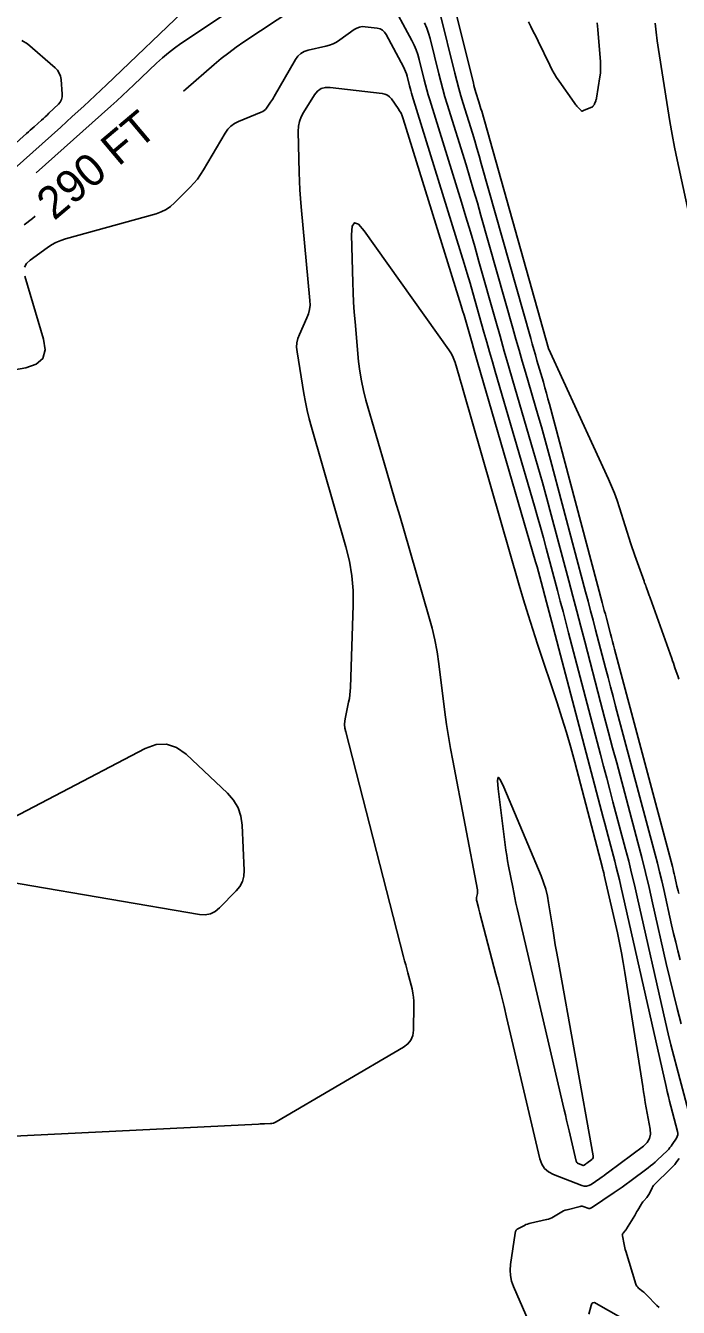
# Model space of a CAD drawing. Extents: x 1768942 to 1774819, y 723037 to 732099.
# Drawn here: x 1770546.4 to 1770667.5, y 726239 to 726476.9 of the extents above; entities that cross this region are included whole.
import ezdxf

# ---------------------------------------------------------------- set-up
doc = ezdxf.new("R2010")
doc.units = 0
doc.layers.add('R_Contour Annot', color=7, linetype='Continuous')
doc.layers.add('R_Contours', color=7, linetype='Continuous')

msp = doc.modelspace()

# ---------------------------------------------------------------- linework, layer by layer
at = {"layer": 'R_Contours'}
for points in [[(1770548.33, 726449.52), (1770562.19, 726461.9), (1770563.27, 726462.88), (1770564.35, 726463.86), (1770565.41, 726464.85), (1770566.47, 726465.85), (1770570.67, 726469.88), (1770571.74, 726470.86), (1770572.85, 726471.79), (1770574, 726472.68), (1770575.19, 726473.52), (1770592.17, 726484.94)], [(1770625, 726484.06), (1770629.42, 726466.21), (1770629.53, 726465.76), (1770629.65, 726465.32), (1770629.77, 726464.89), (1770629.91, 726464.45), (1770630.45, 726462.7), (1770630.58, 726462.27), (1770630.71, 726461.83), (1770630.84, 726461.39), (1770630.97, 726460.95), (1770643.37, 726416.95), (1770643.37, 726416.95), (1770643.38, 726416.93), (1770643.38, 726416.93), (1770654.49, 726392.69), (1770655.07, 726391.39), (1770655.6, 726390.08), (1770656.09, 726388.74), (1770656.53, 726387.4), (1770658.65, 726380.7), (1770658.88, 726379.98), (1770659.12, 726379.27), (1770659.36, 726378.56), (1770659.61, 726377.85), (1770661.08, 726373.76), (1770661.11, 726373.68), (1770661.14, 726373.61), (1770661.16, 726373.53), (1770661.2, 726373.46), (1770661.35, 726373.08), (1770661.37, 726373.05), (1770661.38, 726373.01), (1770661.39, 726372.98), (1770661.41, 726372.95), (1770661.45, 726372.82), (1770661.47, 726372.79), (1770661.48, 726372.75), (1770661.49, 726372.72), (1770661.5, 726372.69), (1770661.92, 726371.5), (1770661.99, 726371.3), (1770662.06, 726371.09), (1770662.14, 726370.88), (1770662.21, 726370.67), (1770666.23, 726359.4), (1770666.39, 726358.98), (1770666.53, 726358.55), (1770666.68, 726358.13), (1770666.83, 726357.7), (1770667.41, 726356), (1770667.55, 726355.57)], [(1770576.87, 726480.72), (1770561.38, 726465.89), (1770559.27, 726463.9), (1770557.16, 726461.92), (1770555.02, 726459.97), (1770552.87, 726458.03), (1770544.22, 726450.31)], [(1770596.1, 726479.98), (1770586.87, 726473.83), (1770585.44, 726472.85), (1770584.04, 726471.82), (1770582.67, 726470.75), (1770581.34, 726469.63), (1770576.08, 726465.08), (1770575.63, 726464.69)], [(1770667.97, 726291.65), (1770667.24, 726294.44), (1770666.54, 726297.23), (1770665.87, 726300.03), (1770665.22, 726302.84), (1770662.68, 726314.09), (1770662.04, 726316.9), (1770661.36, 726319.7), (1770660.66, 726322.5), (1770659.93, 726325.28), (1770656.01, 726340.05), (1770655.26, 726342.87), (1770654.52, 726345.68), (1770653.78, 726348.49), (1770653.04, 726351.31), (1770650.09, 726362.56), (1770649.35, 726365.38), (1770648.61, 726368.19), (1770647.87, 726371), (1770647.12, 726373.81), (1770643.85, 726386.1), (1770643.05, 726389.08), (1770642.23, 726392.06), (1770641.39, 726395.03), (1770640.54, 726398), (1770636.77, 726410.94), (1770635.97, 726413.7), (1770635.17, 726416.47), (1770634.38, 726419.23), (1770633.6, 726422), (1770630.47, 726433.08), (1770629.68, 726435.85), (1770628.88, 726438.61), (1770628.05, 726441.36), (1770627.21, 726444.12), (1770621.32, 726463.08), (1770621.04, 726464), (1770620.78, 726464.93), (1770620.53, 726465.86), (1770620.29, 726466.8), (1770619.36, 726470.54), (1770619.1, 726471.47), (1770618.79, 726472.37), (1770618.42, 726473.25), (1770617.99, 726474.11), (1770613.86, 726481.82)], [(1770667.52, 726315.83), (1770667.4, 726316.28), (1770667.3, 726316.73), (1770667.19, 726317.19), (1770666.78, 726318.99), (1770666.68, 726319.45), (1770666.57, 726319.9), (1770666.46, 726320.35), (1770666.34, 726320.79), (1770655.62, 726361.13), (1770655.43, 726361.86), (1770655.24, 726362.58), (1770655.05, 726363.3), (1770654.86, 726364.02), (1770654.1, 726366.91), (1770653.91, 726367.63), (1770653.72, 726368.35), (1770653.53, 726369.08), (1770653.34, 726369.8), (1770643.55, 726406.6), (1770643.27, 726407.62), (1770642.99, 726408.64), (1770642.71, 726409.66), (1770642.41, 726410.68), (1770641.23, 726414.74), (1770640.93, 726415.76), (1770640.64, 726416.78), (1770640.35, 726417.8), (1770640.06, 726418.81), (1770630.9, 726451.3), (1770630.51, 726452.7), (1770630.1, 726454.09), (1770629.68, 726455.48), (1770629.26, 726456.87), (1770627.54, 726462.42), (1770627.12, 726463.8), (1770626.72, 726465.2), (1770626.34, 726466.6), (1770625.98, 726468.01), (1770623.19, 726479.26)], [(1770546.18, 726432.03), (1770546.56, 726432.74), (1770547.21, 726433.35), (1770550.35, 726435.64), (1770551.15, 726436.17), (1770551.99, 726436.62), (1770552.87, 726437), (1770553.79, 726437.3), (1770570.59, 726441.96), (1770571.54, 726442.29), (1770572.43, 726442.73), (1770573.25, 726443.29), (1770574, 726443.95), (1770576.89, 726446.85), (1770577.58, 726447.6), (1770578.23, 726448.38), (1770578.82, 726449.2), (1770579.36, 726450.07), (1770583.36, 726456.92), (1770583.85, 726457.62), (1770584.42, 726458.21), (1770585.09, 726458.69), (1770585.85, 726459.07), (1770590.07, 726460.78), (1770590.36, 726460.92), (1770590.62, 726461.1), (1770590.85, 726461.31), (1770591.05, 726461.56), (1770591.8, 726462.62), (1770591.99, 726462.89), (1770592.17, 726463.16), (1770592.34, 726463.44), (1770592.5, 726463.72), (1770596.43, 726470.55), (1770596.88, 726471.18), (1770597.42, 726471.68), (1770598.06, 726472.05), (1770598.79, 726472.29), (1770602.05, 726473.02), (1770602.75, 726473.21), (1770603.42, 726473.48), (1770604.06, 726473.8), (1770604.68, 726474.2), (1770607.34, 726476.13), (1770607.81, 726476.41), (1770608.3, 726476.59), (1770608.82, 726476.67), (1770609.36, 726476.64), (1770611.59, 726476.36), (1770612.11, 726476.24), (1770612.55, 726476.01), (1770612.93, 726475.67), (1770613.23, 726475.23), (1770616.47, 726469.19), (1770616.67, 726468.77), (1770616.85, 726468.35), (1770617, 726467.92), (1770617.13, 726467.48), (1770617.57, 726465.69), (1770617.68, 726465.24), (1770617.8, 726464.8), (1770617.93, 726464.35), (1770618.06, 726463.91), (1770627.19, 726434.5), (1770627.74, 726432.69), (1770628.29, 726430.87), (1770628.82, 726429.06), (1770629.34, 726427.24), (1770631.39, 726419.95), (1770631.91, 726418.13), (1770632.43, 726416.31), (1770632.95, 726414.49), (1770633.48, 726412.67), (1770640.76, 726387.67), (1770641.32, 726385.72), (1770641.87, 726383.77), (1770642.41, 726381.82), (1770642.94, 726379.86), (1770645.02, 726372.03), (1770645.54, 726370.07), (1770646.06, 726368.11), (1770646.57, 726366.15), (1770647.09, 726364.19), (1770653, 726341.63), (1770653.58, 726339.43), (1770654.16, 726337.23), (1770654.74, 726335.03), (1770655.32, 726332.83), (1770657.66, 726324.02), (1770658.24, 726321.82), (1770658.79, 726319.61), (1770659.32, 726317.4), (1770659.83, 726315.18), (1770665.08, 726291.91), (1770665.57, 726289.8), (1770666.08, 726287.7), (1770666.6, 726285.6), (1770667.15, 726283.51), (1770670.06, 726272.56)], [(1770620.38, 726477.35), (1770620.78, 726476.41), (1770621.11, 726475.45), (1770621.39, 726474.47), (1770623.01, 726467.91), (1770623.37, 726466.48), (1770623.75, 726465.07), (1770624.16, 726463.66), (1770624.58, 726462.25), (1770628.06, 726451.03), (1770628.78, 726448.69), (1770629.48, 726446.35), (1770630.17, 726444), (1770630.84, 726441.65), (1770636.75, 726420.7), (1770637.32, 726418.66), (1770637.91, 726416.62), (1770638.49, 726414.59), (1770639.08, 726412.55), (1770641.45, 726404.42), (1770642.04, 726402.39), (1770642.61, 726400.35), (1770643.17, 726398.31), (1770643.72, 726396.26), (1770650.23, 726371.81), (1770650.7, 726370.04), (1770651.17, 726368.27), (1770651.63, 726366.5), (1770652.09, 726364.74), (1770653.95, 726357.66), (1770654.41, 726355.9), (1770654.88, 726354.13), (1770655.34, 726352.36), (1770655.81, 726350.59), (1770663.14, 726323.04), (1770663.56, 726321.42), (1770663.97, 726319.8), (1770664.36, 726318.17), (1770664.73, 726316.54), (1770666.21, 726310.01), (1770666.58, 726308.38), (1770666.97, 726306.76), (1770667.38, 726305.14), (1770667.8, 726303.52)], [(1770652.39, 726477.36), (1770652.49, 726476.13), (1770652.99, 726470.12), (1770653.03, 726469.42), (1770653.03, 726468.72), (1770652.98, 726468.02), (1770652.89, 726467.33), (1770652.26, 726463.39), (1770652.24, 726463.27), (1770652.21, 726463.16), (1770652.17, 726463.04), (1770652.13, 726462.92), (1770651.92, 726462.35), (1770651.89, 726462.3), (1770651.87, 726462.24), (1770651.84, 726462.19), (1770651.81, 726462.14), (1770651.68, 726461.94), (1770651.65, 726461.9), (1770651.61, 726461.86), (1770651.56, 726461.82), (1770651.51, 726461.8), (1770649.87, 726461.09), (1770649.87, 726461.09), (1770649.87, 726461.09), (1770649.86, 726461.09), (1770649.86, 726461.09), (1770649.85, 726461.1), (1770649.85, 726461.1), (1770649.84, 726461.1), (1770649.84, 726461.1), (1770649.84, 726461.1), (1770649.62, 726461.01), (1770649.58, 726461), (1770649.55, 726461), (1770649.51, 726461.01), (1770649.48, 726461.03), (1770648.64, 726461.91), (1770648.5, 726462.07), (1770648.36, 726462.23), (1770648.22, 726462.4), (1770648.1, 726462.57), (1770645.36, 726466.52), (1770644.87, 726467.24), (1770644.42, 726467.98), (1770643.99, 726468.74), (1770643.6, 726469.52), (1770641.43, 726473.97), (1770640.99, 726474.87), (1770640.55, 726475.77), (1770640.1, 726476.67), (1770639.66, 726477.57)], [(1770672.35, 726428.26), (1770667.23, 726451.97), (1770666.74, 726454.32), (1770666.28, 726456.68), (1770665.86, 726459.04), (1770665.47, 726461.41), (1770663.76, 726472.4), (1770663.52, 726474.02), (1770663.32, 726475.64), (1770663.16, 726477.28)], [(1770545.69, 726474.12), (1770546.71, 726473.46), (1770551.86, 726469.01), (1770552.29, 726468.56), (1770552.61, 726468.05), (1770552.83, 726467.49), (1770552.94, 726466.88), (1770553.16, 726464.15), (1770553.15, 726463.61), (1770553.03, 726463.12), (1770552.79, 726462.67), (1770552.45, 726462.26), (1770550.69, 726460.58), (1770550.35, 726460.26), (1770550.01, 726459.94), (1770549.67, 726459.63), (1770549.32, 726459.31), (1770547.93, 726458.07), (1770547.58, 726457.76), (1770547.23, 726457.45), (1770546.88, 726457.13), (1770546.53, 726456.82), (1770526.78, 726439.08)], [(1770540.37, 726270.59), (1770589.57, 726273.02), (1770589.85, 726273.04), (1770590.12, 726273.05), (1770590.4, 726273.06), (1770590.68, 726273.07), (1770591.79, 726273.12), (1770592.06, 726273.15), (1770592.33, 726273.21), (1770592.58, 726273.3), (1770592.83, 726273.43), (1770616.49, 726287.32), (1770617.27, 726287.91), (1770617.84, 726288.62), (1770618.18, 726289.46), (1770618.31, 726290.43), (1770618.41, 726295.07), (1770618.4, 726295.83), (1770618.33, 726296.59), (1770618.22, 726297.34), (1770618.05, 726298.09), (1770617.26, 726301.06), (1770617.07, 726301.81), (1770616.87, 726302.55), (1770616.68, 726303.29), (1770616.49, 726304.04), (1770605.74, 726345.81), (1770605.6, 726346.49), (1770605.55, 726347.17), (1770605.58, 726347.86), (1770605.69, 726348.54), (1770606.29, 726351.29), (1770606.42, 726351.97), (1770606.53, 726352.67), (1770606.6, 726353.36), (1770606.64, 726354.06), (1770607.14, 726369.29), (1770607.12, 726372.05), (1770606.89, 726374.78), (1770606.45, 726377.48), (1770605.79, 726380.16), (1770599.4, 726402.36), (1770598.98, 726403.9), (1770598.61, 726405.45), (1770598.28, 726407), (1770598, 726408.57), (1770596.72, 726416.35), (1770596.64, 726417.17), (1770596.69, 726417.98), (1770596.86, 726418.77), (1770597.15, 726419.55), (1770598.56, 726422.62), (1770598.85, 726423.39), (1770599.04, 726424.19), (1770599.13, 726425), (1770599.1, 726425.83), (1770597.5, 726443.21), (1770597.37, 726444.8), (1770597.26, 726446.39), (1770597.19, 726447.98), (1770597.13, 726449.57), (1770596.95, 726457.23), (1770597, 726458.17), (1770597.17, 726459.07), (1770597.48, 726459.93), (1770597.93, 726460.76), (1770599.97, 726464), (1770600.53, 726464.69), (1770601.21, 726465.16), (1770601.99, 726465.39), (1770602.89, 726465.39), (1770612.51, 726464.27), (1770613.02, 726464.16), (1770613.48, 726463.96), (1770613.87, 726463.66), (1770614.21, 726463.26), (1770615.46, 726461.5), (1770615.75, 726461.05), (1770616.01, 726460.58), (1770616.23, 726460.09), (1770616.4, 726459.58), (1770627.17, 726424.88), (1770627.44, 726424.01), (1770627.7, 726423.14), (1770627.95, 726422.27), (1770628.2, 726421.4), (1770629.19, 726417.9), (1770629.43, 726417.03), (1770629.68, 726416.15), (1770629.93, 726415.28), (1770630.19, 726414.41), (1770640.98, 726377.34), (1770641.25, 726376.42), (1770641.51, 726375.49), (1770641.77, 726374.56), (1770642.02, 726373.62), (1770643.01, 726369.89), (1770643.26, 726368.96), (1770643.51, 726368.02), (1770643.75, 726367.09), (1770644, 726366.16), (1770653.18, 726331.09), (1770653.49, 726329.93), (1770653.79, 726328.78), (1770654.1, 726327.62), (1770654.41, 726326.46), (1770655.64, 726321.84), (1770655.94, 726320.68), (1770656.23, 726319.52), (1770656.51, 726318.36), (1770656.78, 726317.19), (1770665.17, 726279.97), (1770665.38, 726279.06), (1770665.6, 726278.16), (1770665.83, 726277.26), (1770666.06, 726276.36), (1770667.31, 726271.66), (1770667.37, 726271.33), (1770667.35, 726271), (1770667.26, 726270.69), (1770667.1, 726270.39), (1770666.32, 726269.21), (1770666.11, 726268.92), (1770665.9, 726268.65), (1770665.66, 726268.39), (1770665.41, 726268.13), (1770663.52, 726266.34), (1770663.12, 726265.97), (1770662.7, 726265.61), (1770662.28, 726265.26), (1770661.84, 726264.92), (1770658.46, 726262.38), (1770657.75, 726261.86), (1770657.02, 726261.34), (1770656.3, 726260.83), (1770655.56, 726260.32), (1770651.35, 726257.48), (1770651.18, 726257.39), (1770651.02, 726257.35), (1770650.85, 726257.35), (1770650.67, 726257.4), (1770649.95, 726257.68), (1770649.78, 726257.73), (1770649.59, 726257.76), (1770649.41, 726257.76), (1770649.23, 726257.73), (1770646.8, 726257.13), (1770646.46, 726257.03), (1770646.13, 726256.9), (1770645.81, 726256.75), (1770645.51, 726256.58), (1770644.31, 726255.82), (1770644.01, 726255.65), (1770643.69, 726255.5), (1770643.36, 726255.38), (1770643.02, 726255.29), (1770640.04, 726254.64), (1770639.75, 726254.57), (1770639.45, 726254.47), (1770639.17, 726254.36), (1770638.89, 726254.23), (1770637.79, 726253.67), (1770637.55, 726253.51), (1770637.36, 726253.31), (1770637.23, 726253.07), (1770637.15, 726252.78), (1770636.31, 726246.99), (1770636.23, 726245.94), (1770636.3, 726244.9), (1770636.51, 726243.89), (1770636.87, 726242.89), (1770640.85, 726233.8)], [(1770548.11, 726441.49), (1770547.62, 726441.08), (1770546.07, 726439.88)], [(1770517.93, 726408.32), (1770546.41, 726413.37), (1770548.35, 726414.01), (1770549.55, 726415.11), (1770549.99, 726416.67), (1770549.69, 726418.69), (1770546.2, 726430.35)], [(1770534.98, 726325.17), (1770568.53, 726342.7), (1770570.57, 726343.45), (1770572.51, 726343.53), (1770574.36, 726342.93), (1770576.12, 726341.66), (1770583.82, 726334.42), (1770584.96, 726333.14), (1770585.79, 726331.72), (1770586.32, 726330.16), (1770586.55, 726328.46), (1770586.89, 726320.06), (1770586.84, 726319), (1770586.58, 726318.01), (1770586.11, 726317.11), (1770585.44, 726316.28), (1770582.34, 726313.13), (1770581.53, 726312.46), (1770580.64, 726312.04), (1770579.67, 726311.86), (1770578.62, 726311.92), (1770528.69, 726320.45)], [(1770667.6, 726266.63), (1770667.2, 726266.07), (1770666.78, 726265.53), (1770666.32, 726265.01), (1770665.83, 726264.52), (1770663.2, 726262.02), (1770663.01, 726261.83), (1770662.85, 726261.63), (1770662.71, 726261.41), (1770662.58, 726261.18), (1770662.08, 726260.14), (1770661.98, 726259.94), (1770661.87, 726259.76), (1770661.74, 726259.59), (1770661.61, 726259.42), (1770661.03, 726258.77), (1770660.89, 726258.6), (1770660.76, 726258.43), (1770660.64, 726258.25), (1770660.53, 726258.07), (1770659.92, 726257.02), (1770659.78, 726256.78), (1770659.64, 726256.55), (1770659.49, 726256.31), (1770659.35, 726256.08), (1770657.82, 726253.56), (1770657.75, 726253.46), (1770657.68, 726253.35), (1770657.6, 726253.25), (1770657.52, 726253.15), (1770657.19, 726252.76), (1770657.12, 726252.66), (1770657.07, 726252.55), (1770657.06, 726252.44), (1770657.07, 726252.31), (1770657.38, 726250.68), (1770657.44, 726250.37), (1770657.51, 726250.05), (1770657.59, 726249.75), (1770657.68, 726249.44), (1770659.56, 726243.34), (1770659.65, 726243.12), (1770659.76, 726242.92), (1770659.91, 726242.74), (1770660.08, 726242.58), (1770660.84, 726241.97), (1770661.03, 726241.81), (1770661.21, 726241.65), (1770661.39, 726241.49), (1770661.56, 726241.31), (1770663.49, 726239.34), (1770663.89, 726238.97)], [(1770650.87, 726237.76), (1770651.28, 726239.37), (1770651.41, 726239.7), (1770651.61, 726239.87), (1770651.88, 726239.89), (1770652.2, 726239.76), (1770658.61, 726236.1)]]:
    msp.add_lwpolyline(points, dxfattribs=at)
for points in [[(1770630.56, 726312.41), (1770630.49, 726312.67), (1770630.42, 726312.93), (1770630.35, 726313.19), (1770630.04, 726314.4), (1770630.01, 726314.57), (1770630, 726314.74), (1770630, 726314.91), (1770630.03, 726315.09), (1770630.18, 726315.78), (1770630.21, 726315.96), (1770630.22, 726316.13), (1770630.22, 726316.3), (1770630.19, 726316.48), (1770625.59, 726340.5), (1770625.18, 726342.72), (1770624.81, 726344.95), (1770624.47, 726347.19), (1770624.16, 726349.43), (1770623.02, 726358.41), (1770622.69, 726360.64), (1770622.27, 726362.86), (1770621.77, 726365.06), (1770621.18, 726367.24), (1770616.57, 726383.12), (1770615.76, 726385.9), (1770614.95, 726388.67), (1770614.14, 726391.45), (1770613.33, 726394.23), (1770609.5, 726407.37), (1770609.03, 726409.14), (1770608.65, 726410.93), (1770608.35, 726412.73), (1770608.14, 726414.55), (1770607.47, 726421.86), (1770607.31, 726423.69), (1770607.19, 726425.52), (1770607.1, 726427.36), (1770607.04, 726429.19), (1770606.83, 726438.01), (1770606.94, 726439.62), (1770607.36, 726440.28), (1770608.1, 726440), (1770609.15, 726438.78), (1770624.89, 726416.68), (1770625.25, 726416.12), (1770625.56, 726415.55), (1770625.83, 726414.95), (1770626.04, 726414.33), (1770626.81, 726411.79), (1770627, 726411.15), (1770627.19, 726410.52), (1770627.37, 726409.88), (1770627.56, 726409.24), (1770637.94, 726373.03), (1770638.75, 726370.28), (1770639.58, 726367.53), (1770640.45, 726364.79), (1770641.34, 726362.06), (1770644.97, 726351.16), (1770645.85, 726348.43), (1770646.69, 726345.68), (1770647.49, 726342.92), (1770648.24, 726340.15), (1770653.37, 726320.55), (1770653.4, 726320.44), (1770653.43, 726320.33), (1770653.46, 726320.22), (1770653.49, 726320.1), (1770653.61, 726319.66), (1770653.64, 726319.55), (1770653.67, 726319.43), (1770653.69, 726319.32), (1770653.72, 726319.21), (1770656.14, 726308.49), (1770656.53, 726306.66), (1770656.9, 726304.83), (1770657.23, 726302.99), (1770657.54, 726301.15), (1770660.84, 726279.98), (1770660.99, 726278.99), (1770661.15, 726278), (1770661.32, 726277.02), (1770661.5, 726276.04), (1770662.21, 726272.1), (1770662.26, 726271.17), (1770662.07, 726270.33), (1770661.64, 726269.59), (1770660.96, 726268.94), (1770654.48, 726264.08), (1770654.09, 726263.79), (1770653.69, 726263.5), (1770653.29, 726263.22), (1770652.88, 726262.94), (1770651.25, 726261.84), (1770650.84, 726261.62), (1770650.41, 726261.52), (1770649.97, 726261.53), (1770649.52, 726261.65), (1770644.31, 726263.67), (1770643.38, 726264.15), (1770642.65, 726264.8), (1770642.11, 726265.61), (1770641.76, 726266.59), (1770635.6, 726292.84), (1770635.13, 726294.83), (1770634.64, 726296.82), (1770634.14, 726298.8), (1770633.62, 726300.79), (1770630.62, 726312.15)], [(1770635.78, 726321.89), (1770635.62, 726322.89), (1770635.47, 726323.88), (1770635.33, 726324.87), (1770634.01, 726335.24), (1770633.88, 726336.8), (1770634.02, 726337.37), (1770634.42, 726336.95), (1770635.09, 726335.53), (1770641.98, 726319.06), (1770642.45, 726317.84), (1770642.84, 726316.6), (1770643.15, 726315.34), (1770643.39, 726314.06), (1770644.2, 726308.89), (1770644.4, 726307.6), (1770644.62, 726306.31), (1770644.84, 726305.02), (1770645.07, 726303.73), (1770651.66, 726267.13), (1770651.67, 726266.92), (1770651.63, 726266.74), (1770651.53, 726266.58), (1770651.39, 726266.44), (1770650.47, 726265.76), (1770650.41, 726265.71), (1770650.35, 726265.67), (1770650.29, 726265.62), (1770650.23, 726265.58), (1770649.97, 726265.41), (1770649.91, 726265.38), (1770649.84, 726265.36), (1770649.77, 726265.36), (1770649.7, 726265.38), (1770648.89, 726265.69), (1770648.75, 726265.77), (1770648.63, 726265.87), (1770648.55, 726266), (1770648.49, 726266.15), (1770647.18, 726271.74), (1770646.95, 726272.73), (1770646.72, 726273.72), (1770646.49, 726274.71), (1770646.26, 726275.69), (1770637.56, 726313.03), (1770637.33, 726314.01), (1770637.12, 726314.99), (1770636.92, 726315.98), (1770636.72, 726316.96), (1770635.96, 726320.91)]]:
    msp.add_lwpolyline(points, close=True, dxfattribs=at)

# ---------------------------------------------------------------- texts
at = {"layer": 'R_Contour Annot'}
msp.add_text('290 FT', height=6, rotation=40.136, dxfattribs=at).set_placement((1770551.65, 726440.55))

doc.saveas('drawing.dxf')
